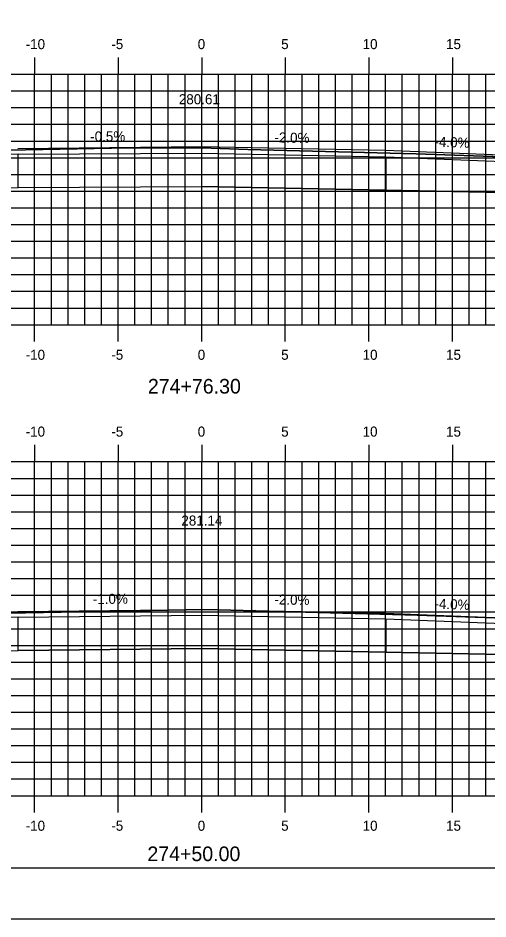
# Model space of a CAD drawing. Extents: x 853340 to 853510, y 366268 to 366378.
# Drawn here: x 853412.1 to 853440.2, y 366268.2 to 366322.1 of the extents above; entities that cross this region are included whole.
import ezdxf

# ---------------------------------------------------------------- set-up
doc = ezdxf.new("R2010")
doc.units = 0
for name, color, linetype in [('ANNOTATION', 7, 'Continuous'), ('BORDER', 7, 'Continuous'), ('D_Roadway_Centerline_Text', 7, 'Continuous'), ('D_Roadway_Edge_TW', 7, 'Continuous'), ('D_Roadway_SubGrade', 7, 'Continuous'), ('H_V ANNOTATION', 7, 'Continuous'), ('JUNK COM EXC', 7, 'Continuous'), ('MAJOR', 7, 'Continuous'), ('MINOR', 7, 'Continuous'), ('PLOT BOUNDARY', 7, 'Continuous'), ('S_Roadway_Centerline', 7, 'Continuous')]:
    doc.layers.add(name, color=color, linetype=linetype)

msp = doc.modelspace()

# ---------------------------------------------------------------- linework, layer by layer
at = {"layer": 'BORDER'}
msp.add_line((853348.1, 366271.236), (853508.1, 366271.236), dxfattribs=at)
at = {"layer": 'D_Roadway_Edge_TW'}
for p, q in [((853412.1, 366314.305), (853423.1, 366314.419)), ((853423.1, 366314.419), (853434.1, 366314.199)), ((853434.1, 366314.199), (853442.1, 366313.879))]:
    msp.add_line(p, q, dxfattribs=at)
msp.add_lwpolyline([(853404.1, 366286.267), (853412.1, 366286.587), (853423.1, 366286.701), (853434.1, 366286.48), (853442.1, 366286.16)], dxfattribs=at)
at = {"layer": 'D_Roadway_SubGrade'}
for p, q in [((853412.108, 366313.972), (853423.108, 366314.03)), ((853423.108, 366314.03), (853434.108, 366313.81)), ((853434.108, 366313.81), (853434.108, 366311.81)), ((853412.108, 366311.972), (853423.108, 366312.03)), ((853434.108, 366311.81), (853423.108, 366312.03))]:
    msp.add_line(p, q, dxfattribs=at)
for points in [[(853403.1, 366311.792), (853412.108, 366311.972), (853412.108, 366313.972), (853404.1, 366313.652)], [(853443.1, 366311.63), (853434.108, 366311.81), (853434.108, 366313.81), (853442.1, 366313.49)], [(853403.1, 366284.074), (853412.108, 366284.254), (853412.108, 366286.254), (853404.1, 366285.933)], [(853443.1, 366283.968), (853434.108, 366284.148), (853434.108, 366286.148), (853442.1, 366285.828)]]:
    msp.add_lwpolyline(points, dxfattribs=at)
msp.add_lwpolyline([(853412.108, 366284.254), (853412.108, 366286.254), (853423.108, 366286.368), (853434.108, 366286.148), (853434.108, 366284.148), (853423.108, 366284.368)], close=True, dxfattribs=at)
at = {"layer": 'JUNK COM EXC'}
for points in [[(853403.1, 366313.783), (853403.1, 366311.792), (853412.108, 366311.972), (853423.108, 366312.03), (853443.1, 366311.63), (853443.1, 366313.251), (853447.105, 366313.332), (853447.105, 366313.648), (853444.01, 366313.735), (853443.885, 366313.73), (853441.643, 366313.789), (853435.938, 366313.988), (853425.848, 366314.256), (853423.1, 366314.352), (853417.701, 366314.327), (853411.542, 366314.212), (853408.292, 366314.075), (853404.573, 366313.84), (853403.1, 366313.783)], [(853403.1, 366285.982), (853403.1, 366284.074), (853412.108, 366284.254), (853423.108, 366284.368), (853443.1, 366283.968), (853443.1, 366285.588), (853447.105, 366285.669), (853447.105, 366286.025), (853442.522, 366286.163), (853440.609, 366286.208), (853435.982, 366286.375), (853424.096, 366286.691), (853423.104, 366286.714), (853422.159, 366286.693), (853411.503, 366286.496), (853410.582, 366286.432), (853404.575, 366286.053), (853403.1, 366285.982)]]:
    msp.add_lwpolyline(points, dxfattribs=at)
at = {"layer": 'MAJOR'}
for p, q in [((853413.1, 366319.759), (853413.1, 366318.757)), ((853418.1, 366319.759), (853418.1, 366318.757)), ((853423.1, 366319.759), (853423.1, 366318.757)), ((853428.1, 366319.759), (853428.1, 366318.757)), ((853433.1, 366319.759), (853433.1, 366318.757)), ((853438.1, 366319.759), (853438.1, 366318.757)), ((853353.1, 366318.757), (853493.1, 366318.757)), ((853353.1, 366318.757), (853493.1, 366318.757)), ((853413.1, 366303.757), (853413.1, 366318.757)), ((853418.1, 366303.757), (853418.1, 366318.757)), ((853423.1, 366303.757), (853423.1, 366318.757)), ((853428.1, 366303.757), (853428.1, 366318.757)), ((853433.1, 366303.757), (853433.1, 366318.757)), ((853438.1, 366303.757), (853438.1, 366318.757)), ((853353.1, 366313.757), (853493.1, 366313.757)), ((853353.1, 366308.757), (853493.1, 366308.757)), ((853353.1, 366303.757), (853493.1, 366303.757)), ((853413.1, 366302.755), (853413.1, 366303.757)), ((853418.1, 366302.755), (853418.1, 366303.757)), ((853423.1, 366302.755), (853423.1, 366303.757)), ((853428.1, 366302.755), (853428.1, 366303.757)), ((853433.1, 366302.755), (853433.1, 366303.757)), ((853438.1, 366302.755), (853438.1, 366303.757)), ((853413.1, 366296.561), (853413.1, 366295.559)), ((853418.1, 366296.561), (853418.1, 366295.559)), ((853423.1, 366296.561), (853423.1, 366295.559)), ((853428.1, 366296.561), (853428.1, 366295.559)), ((853433.1, 366296.561), (853433.1, 366295.559)), ((853438.1, 366296.561), (853438.1, 366295.559)), ((853353.1, 366295.559), (853493.1, 366295.559)), ((853353.1, 366295.559), (853493.1, 366295.559)), ((853413.1, 366275.559), (853413.1, 366295.559)), ((853418.1, 366275.559), (853418.1, 366295.559)), ((853423.1, 366275.559), (853423.1, 366295.559)), ((853428.1, 366275.559), (853428.1, 366295.559)), ((853433.1, 366275.559), (853433.1, 366295.559)), ((853438.1, 366275.559), (853438.1, 366295.559)), ((853353.1, 366290.559), (853493.1, 366290.559)), ((853353.1, 366285.559), (853493.1, 366285.559)), ((853353.1, 366280.559), (853493.1, 366280.559)), ((853353.1, 366275.559), (853493.1, 366275.559)), ((853353.1, 366275.559), (853493.1, 366275.559)), ((853413.1, 366274.557), (853413.1, 366275.559)), ((853418.1, 366274.557), (853418.1, 366275.559)), ((853423.1, 366274.557), (853423.1, 366275.559)), ((853428.1, 366274.557), (853428.1, 366275.559)), ((853433.1, 366274.557), (853433.1, 366275.559)), ((853438.1, 366274.557), (853438.1, 366275.559))]:
    msp.add_line(p, q, dxfattribs=at)
at = {"layer": 'MINOR'}
for p, q in [((853414.1, 366303.757), (853414.1, 366318.757)), ((853415.1, 366303.757), (853415.1, 366318.757)), ((853416.1, 366303.757), (853416.1, 366318.757)), ((853417.1, 366303.757), (853417.1, 366318.757)), ((853419.1, 366303.757), (853419.1, 366318.757)), ((853420.1, 366303.757), (853420.1, 366318.757)), ((853421.1, 366303.757), (853421.1, 366318.757)), ((853422.1, 366303.757), (853422.1, 366318.757)), ((853424.1, 366303.757), (853424.1, 366318.757)), ((853425.1, 366303.757), (853425.1, 366318.757)), ((853426.1, 366303.757), (853426.1, 366318.757)), ((853427.1, 366303.757), (853427.1, 366318.757)), ((853429.1, 366303.757), (853429.1, 366318.757)), ((853430.1, 366303.757), (853430.1, 366318.757)), ((853431.1, 366303.757), (853431.1, 366318.757)), ((853432.1, 366303.757), (853432.1, 366318.757)), ((853434.1, 366303.757), (853434.1, 366318.757)), ((853435.1, 366303.757), (853435.1, 366318.757)), ((853436.1, 366303.757), (853436.1, 366318.757)), ((853437.1, 366303.757), (853437.1, 366318.757)), ((853439.1, 366303.757), (853439.1, 366318.757)), ((853440.1, 366303.757), (853440.1, 366318.757)), ((853353.1, 366317.757), (853493.1, 366317.757)), ((853353.1, 366316.757), (853493.1, 366316.757)), ((853353.1, 366315.757), (853493.1, 366315.757)), ((853353.1, 366314.757), (853493.1, 366314.757)), ((853353.1, 366312.757), (853493.1, 366312.757)), ((853353.1, 366311.757), (853493.1, 366311.757)), ((853353.1, 366310.757), (853493.1, 366310.757)), ((853353.1, 366309.757), (853493.1, 366309.757)), ((853353.1, 366307.757), (853493.1, 366307.757)), ((853353.1, 366306.757), (853493.1, 366306.757)), ((853353.1, 366305.757), (853493.1, 366305.757)), ((853353.1, 366304.757), (853493.1, 366304.757)), ((853414.1, 366275.559), (853414.1, 366295.559)), ((853415.1, 366275.559), (853415.1, 366295.559)), ((853416.1, 366275.559), (853416.1, 366295.559)), ((853417.1, 366275.559), (853417.1, 366295.559)), ((853419.1, 366275.559), (853419.1, 366295.559)), ((853420.1, 366275.559), (853420.1, 366295.559)), ((853421.1, 366275.559), (853421.1, 366295.559)), ((853422.1, 366275.559), (853422.1, 366295.559)), ((853424.1, 366275.559), (853424.1, 366295.559)), ((853425.1, 366275.559), (853425.1, 366295.559)), ((853426.1, 366275.559), (853426.1, 366295.559)), ((853427.1, 366275.559), (853427.1, 366295.559)), ((853429.1, 366275.559), (853429.1, 366295.559)), ((853430.1, 366275.559), (853430.1, 366295.559)), ((853431.1, 366275.559), (853431.1, 366295.559)), ((853432.1, 366275.559), (853432.1, 366295.559)), ((853434.1, 366275.559), (853434.1, 366295.559)), ((853435.1, 366275.559), (853435.1, 366295.559)), ((853436.1, 366275.559), (853436.1, 366295.559)), ((853437.1, 366275.559), (853437.1, 366295.559)), ((853439.1, 366275.559), (853439.1, 366295.559)), ((853440.1, 366275.559), (853440.1, 366295.559)), ((853353.1, 366294.559), (853493.1, 366294.559)), ((853353.1, 366293.559), (853493.1, 366293.559)), ((853353.1, 366292.559), (853493.1, 366292.559)), ((853353.1, 366291.559), (853493.1, 366291.559)), ((853353.1, 366289.559), (853493.1, 366289.559)), ((853353.1, 366288.559), (853493.1, 366288.559)), ((853353.1, 366287.559), (853493.1, 366287.559)), ((853353.1, 366286.559), (853493.1, 366286.559)), ((853353.1, 366284.559), (853493.1, 366284.559)), ((853353.1, 366283.559), (853493.1, 366283.559)), ((853353.1, 366282.559), (853493.1, 366282.559)), ((853353.1, 366281.559), (853493.1, 366281.559)), ((853353.1, 366279.559), (853493.1, 366279.559)), ((853353.1, 366278.559), (853493.1, 366278.559)), ((853353.1, 366277.559), (853493.1, 366277.559)), ((853353.1, 366276.559), (853493.1, 366276.559))]:
    msp.add_line(p, q, dxfattribs=at)
at = {"layer": 'PLOT BOUNDARY'}
msp.add_lwpolyline([(853340.007, 366268.177), (853510.007, 366268.177), (853510.007, 366378.177), (853340.007, 366378.177)], close=True, dxfattribs=at)
at = {"layer": 'S_Roadway_Centerline'}
for points in [[(853390.695, 366312.884), (853396.582, 366312.962), (853402.362, 366313.754), (853404.573, 366313.84), (853408.292, 366314.075), (853411.542, 366314.212), (853417.701, 366314.327), (853423.1, 366314.352), (853425.848, 366314.256), (853435.938, 366313.988), (853441.643, 366313.789), (853443.885, 366313.73), (853444.01, 366313.735), (853448.826, 366313.6), (853449.069, 366313.813), (853449.359, 366313.991), (853449.683, 366313.823), (853449.767, 366313.833), (853452.013, 366313.927), (853454.293, 366314.022), (853454.426, 366314.05), (853454.571, 366314.069)], [(853378.002, 366284.035), (853391.663, 366284.218), (853393.728, 366284.501), (853401.276, 366285.894), (853404.575, 366286.053), (853410.582, 366286.432), (853411.503, 366286.496), (853422.159, 366286.693), (853423.104, 366286.714), (853424.096, 366286.691), (853435.982, 366286.375), (853440.609, 366286.208), (853442.522, 366286.163), (853448.883, 366285.971), (853449.042, 366286.069), (853449.557, 366286.324), (853451.29, 366286.654), (853460.175, 366287.602), (853462.142, 366287.892)]]:
    msp.add_lwpolyline(points, dxfattribs=at)

# ---------------------------------------------------------------- texts
at = {"layer": 'ANNOTATION'}
for s, rotation, p in [('-0.5%', 0.3022, (853416.428, 366314.728)), ('-2.0%', 358.8542, (853427.443, 366314.676)), ('-4.0%', 357.7095, (853437.014, 366314.427)), ('-1.0%', 0.593, (853416.584, 366287.033)), ('-2.0%', 358.8542, (853427.443, 366287.014)), ('-4.0%', 357.7095, (853437.014, 366286.765))]:
    msp.add_text(s, height=0.6, rotation=rotation, dxfattribs=at).set_placement(p)
at = {"layer": 'D_Roadway_Centerline_Text'}
for s, p in [('280.61', (853421.73, 366316.958)), ('281.14', (853421.88, 366291.733))]:
    msp.add_text(s, height=0.6, dxfattribs=at).set_placement(p)
at = {"layer": 'H_V ANNOTATION'}
for s, height, p in [('-10', 0.6, (853412.565, 366320.257)), ('-5', 0.6, (853417.69, 366320.257)), ('0', 0.6, (853422.859, 366320.257)), ('5', 0.6, (853427.851, 366320.257)), ('10', 0.6, (853432.725, 366320.257)), ('15', 0.6, (853437.717, 366320.257)), ('-10', 0.6, (853412.565, 366301.657)), ('-5', 0.6, (853417.69, 366301.657)), ('0', 0.6, (853422.859, 366301.657)), ('5', 0.6, (853427.851, 366301.657)), ('10', 0.6, (853432.725, 366301.657)), ('15', 0.6, (853437.717, 366301.657)), ('274+76.30', 0.875, (853419.877, 366299.636)), ('-10', 0.6, (853412.565, 366297.059)), ('-5', 0.6, (853417.69, 366297.059)), ('0', 0.6, (853422.859, 366297.059)), ('5', 0.6, (853427.851, 366297.059)), ('10', 0.6, (853432.725, 366297.059)), ('15', 0.6, (853437.717, 366297.059)), ('-10', 0.6, (853412.565, 366273.459)), ('-5', 0.6, (853417.69, 366273.459)), ('0', 0.6, (853422.859, 366273.459)), ('5', 0.6, (853427.851, 366273.459)), ('10', 0.6, (853432.725, 366273.459)), ('15', 0.6, (853437.717, 366273.459)), ('274+50.00', 0.875, (853419.846, 366271.642))]:
    msp.add_text(s, height=height, dxfattribs=at).set_placement(p)
at = {"layer": 'S_Roadway_Centerline'}
for s, p in [('C', (853423.095, 366309.352)), ('L', (853423.1, 366309.345)), ('C', (853423.098, 366286.714)), ('L', (853423.104, 366286.706))]:
    msp.add_text(s, height=0.0146, dxfattribs=at).set_placement(p)

doc.saveas('drawing.dxf')
